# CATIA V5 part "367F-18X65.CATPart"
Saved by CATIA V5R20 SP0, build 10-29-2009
Part number: 367F-18X65
Definition: NONE
Nomenclature: 367F-18X65
Source: Unknown
Description: 367F-18X65
Bounding box of the stored display mesh (mm): x 0 to 65, y -14 to 14, z -14 to 14
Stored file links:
  C:\Users\Utente\Desktop\IO LAVORO\3D X SITO CF\X SITO\PLASTICA\3D files 367\367F-18X65.CATPart
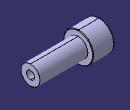
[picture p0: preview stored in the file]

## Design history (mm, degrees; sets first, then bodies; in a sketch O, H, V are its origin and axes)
Body1 "367F-18X65" (main body)
  Solid1: solid without history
